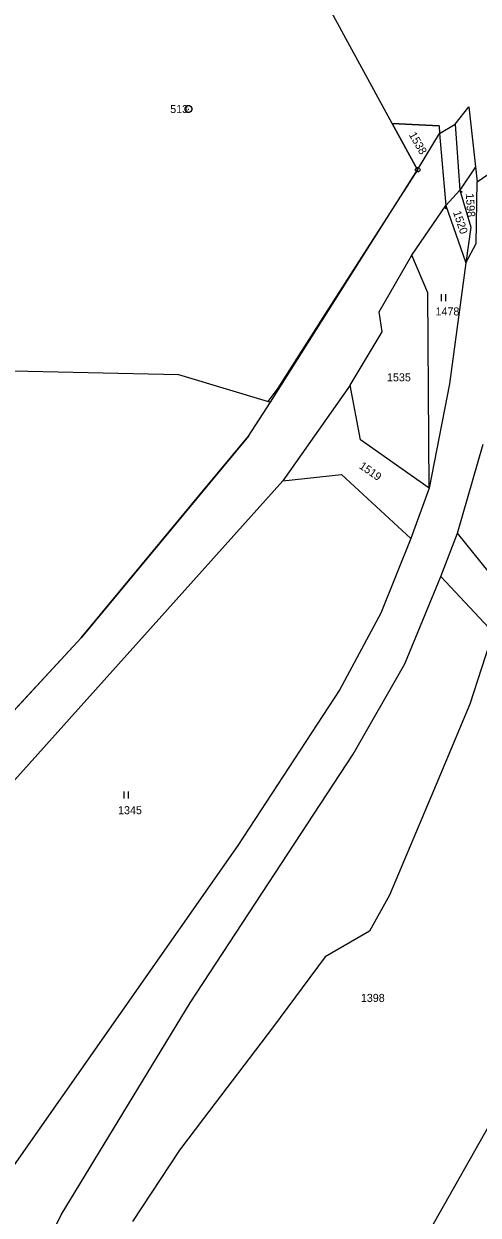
# Model space of a CAD drawing. Extents: x -792913 to -792113, y -1112764 to -1111548.
# Drawn here: x -792564 to -792467.5, y -1111943.5 to -1111690.4 of the extents above; entities that cross this region are included whole.
import ezdxf

# ---------------------------------------------------------------- set-up
doc = ezdxf.new("R2010")
doc.units = 0
for name, color, linetype in [('Vrstva 1', 7, 'Continuous'), ('Vrstva 11', 7, 'Continuous'), ('Vrstva 2', 7, 'Continuous'), ('Vrstva 3', 7, 'Continuous'), ('Vrstva 4', 7, 'Continuous'), ('Vrstva 8', 7, 'Continuous')]:
    doc.layers.add(name, color=color, linetype=linetype)

msp = doc.modelspace()

# ---------------------------------------------------------------- linework, layer by layer
at = {"layer": 'Vrstva 1'}
for p, q in [((-792485.77, -1111711.57), (-792506.06, -1111674.4)), ((-792472.44, -1111711.74), (-792469.49, -1111708.06)), ((-792469.49, -1111708.06), (-792468.11, -1111720.8)), ((-792475.81, -1111712.09), (-792485.77, -1111711.57)), ((-792480.39, -1111721.44), (-792485.77, -1111711.57)), ((-792475.74, -1111713.71), (-792472.44, -1111711.74)), ((-792480.39, -1111721.44), (-792475.74, -1111713.71)), ((-792475.81, -1111712.09), (-792475.74, -1111713.71)), ((-792511.65, -1111770.81), (-792480.39, -1111721.44)), ((-792468.11, -1111720.8), (-792471.44, -1111725.75)), ((-792468.11, -1111720.8), (-792467.76, -1111724.02)), ((-792467.76, -1111724.02), (-792461.41, -1111719.58)), ((-792467.99, -1111737.1), (-792467.76, -1111724.02)), ((-792471.44, -1111725.75), (-792474.4, -1111729.01)), ((-792471.44, -1111725.75), (-792469.1, -1111733.64)), ((-792481.63, -1111739.54), (-792474.4, -1111729.01)), ((-792474.4, -1111729.01), (-792470.14, -1111741.16)), ((-792469.1, -1111733.64), (-792470.14, -1111741.16)), ((-792470.14, -1111741.16), (-792467.99, -1111737.1)), ((-792488.57, -1111751.6), (-792481.63, -1111739.54)), ((-792478.21, -1111747.58), (-792481.63, -1111739.54)), ((-792470.14, -1111741.16), (-792473.65, -1111766.88)), ((-792477.95, -1111789.03), (-792478.21, -1111747.58)), ((-792487.93, -1111755.84), (-792488.57, -1111751.6)), ((-792494.7, -1111767.15), (-792487.93, -1111755.84)), ((-792583.82, -1111763.78), (-792531.13, -1111764.91)), ((-792531.13, -1111764.91), (-792511.65, -1111770.81)), ((-792494.7, -1111767.15), (-792509.03, -1111787.52)), ((-792492.55, -1111778.82), (-792494.7, -1111767.15)), ((-792473.65, -1111766.88), (-792477.95, -1111789.03)), ((-792516.32, -1111777.99), (-792511.65, -1111770.81)), ((-792516.32, -1111777.99), (-792551.84, -1111820.82)), ((-792477.95, -1111789.03), (-792492.55, -1111778.82)), ((-792471.93, -1111798.6), (-792466.47, -1111779.7)), ((-792593.52, -1111881.8), (-792509.03, -1111787.52)), ((-792509.03, -1111787.52), (-792496.54, -1111786.14)), ((-792496.54, -1111786.14), (-792481.82, -1111799.75)), ((-792477.95, -1111789.03), (-792481.82, -1111799.75)), ((-792481.82, -1111799.75), (-792488.22, -1111815.61)), ((-792475.49, -1111807.79), (-792471.93, -1111798.6)), ((-792453.26, -1111821.81), (-792471.93, -1111798.6)), ((-792483.13, -1111826.39), (-792475.49, -1111807.79)), ((-792475.49, -1111807.79), (-792463.17, -1111820.95)), ((-792488.22, -1111815.61), (-792496.94, -1111831.79)), ((-792551.84, -1111820.82), (-792587.75, -1111859.81)), ((-792494.1, -1111845.56), (-792483.13, -1111826.39)), ((-792496.94, -1111831.79), (-792518.6, -1111864.97)), ((-792528.71, -1111898.39), (-792494.1, -1111845.56)), ((-792518.6, -1111864.97), (-792568.49, -1111936.3)), ((-792556.1, -1111943.37), (-792528.71, -1111898.39)), ((-792464.99, -1111924), (-792503.77, -1111992.47)), ((-792560.46, -1111952.54), (-792556.1, -1111943.37))]:
    msp.add_line(p, q, dxfattribs=at)
at = {"layer": 'Vrstva 11'}
for p, q in [((-792472.44, -1111711.74), (-792469.49, -1111708.06)), ((-792469.49, -1111708.06), (-792468.11, -1111720.8)), ((-792485.77, -1111711.57), (-792480.39, -1111721.44)), ((-792485.77, -1111711.57), (-792475.81, -1111712.09)), ((-792475.74, -1111713.71), (-792472.44, -1111711.74)), ((-792475.81, -1111712.09), (-792475.74, -1111713.71)), ((-792480.39, -1111721.44), (-792500, -1111752.06)), ((-792468.11, -1111720.8), (-792467.76, -1111724.02)), ((-792467.76, -1111724.02), (-792461.41, -1111719.58)), ((-792500, -1111752.06), (-792510.1, -1111767.83)), ((-792510.1, -1111767.83), (-792512.17, -1111770.65)), ((-792516.32, -1111777.99), (-792511.65, -1111770.81)), ((-792511.65, -1111770.81), (-792512.17, -1111770.65)), ((-792526.87, -1111790.71), (-792516.32, -1111777.99)), ((-792551.84, -1111820.82), (-792526.87, -1111790.71)), ((-792464.39, -1111819.65), (-792469.33, -1111834.96)), ((-792567.53, -1111837.85), (-792551.84, -1111820.82)), ((-792469.33, -1111834.96), (-792476.47, -1111851.96)), ((-792476.47, -1111851.96), (-792486.37, -1111875.51)), ((-792486.37, -1111875.51), (-792490.62, -1111883.12)), ((-792490.62, -1111883.12), (-792500, -1111888.58)), ((-792500, -1111888.58), (-792511.2, -1111903.68)), ((-792511.2, -1111903.68), (-792525.82, -1111922.96)), ((-792525.82, -1111922.96), (-792530.98, -1111929.67)), ((-792530.98, -1111929.67), (-792540.9, -1111944.78))]:
    msp.add_line(p, q, dxfattribs=at)
at = {"layer": 'Vrstva 3'}
for p, q in [((-792475.41, -1111747.82), (-792475.41, -1111749.32)), ((-792474.41, -1111749.32), (-792474.41, -1111747.82)), ((-792542.79, -1111853.45), (-792542.79, -1111854.95)), ((-792541.79, -1111854.95), (-792541.79, -1111853.45))]:
    msp.add_line(p, q, dxfattribs=at)
at = {"layer": 'Vrstva 4'}
for p, q in [((-792472.44, -1111711.74), (-792471.44, -1111725.75)), ((-792475.74, -1111713.71), (-792474.4, -1111729.01)), ((-792471.44, -1111725.75), (-792470.906, -1111726.213)), ((-792474.4, -1111729.01), (-792474.494, -1111729.711))]:
    msp.add_line(p, q, dxfattribs=at)
at = {"layer": 'Vrstva 8'}
for p, q in [((-792529.1, -1111708.53), (-792529, -1111708.53)), ((-792480.51, -1111721.44), (-792480.27, -1111721.44))]:
    msp.add_line(p, q, dxfattribs=at)
for points in [[(-792528.86, -1111707.81), (-792528.52, -1111708), (-792528.33, -1111708.34), (-792528.33, -1111708.73), (-792528.52, -1111709.07), (-792528.86, -1111709.26), (-792529.25, -1111709.26), (-792529.59, -1111709.07), (-792529.78, -1111708.73), (-792529.78, -1111708.34), (-792529.59, -1111708), (-792529.25, -1111707.81)], [(-792480.24, -1111720.96), (-792479.99, -1111721.14), (-792479.89, -1111721.43), (-792479.99, -1111721.72), (-792480.24, -1111721.9), (-792480.55, -1111721.9), (-792480.8, -1111721.72), (-792480.9, -1111721.43), (-792480.8, -1111721.14), (-792480.55, -1111720.96)]]:
    msp.add_lwpolyline(points, close=True, dxfattribs=at)

# ---------------------------------------------------------------- texts
at = {"layer": 'Vrstva 2'}
for s, rotation, p in [('1538', 300.0007, (-792482.324, -1111713.99)), ('1598', 273.87383, (-792470.183, -1111726.482)), ('1520', 288.77073, (-792472.904, -1111730.452)), ('1519', 325.32544, (-792492.967, -1111784.703))]:
    msp.add_text(s, height=1.7, rotation=rotation, dxfattribs=at).set_placement(p)
for s, p in [('1478', (-792476.597, -1111752.37)), ('1535', (-792486.897, -1111766.36)), ('1345', (-792543.987, -1111858.3)), ('1398', (-792492.447, -1111898.17))]:
    msp.add_text(s, height=1.7, dxfattribs=at).set_placement(p)
at = {"layer": 'Vrstva 8'}
msp.add_text('513', height=1.7, dxfattribs=at).set_placement((-792532.924, -1111709.38))

doc.saveas('drawing.dxf')
